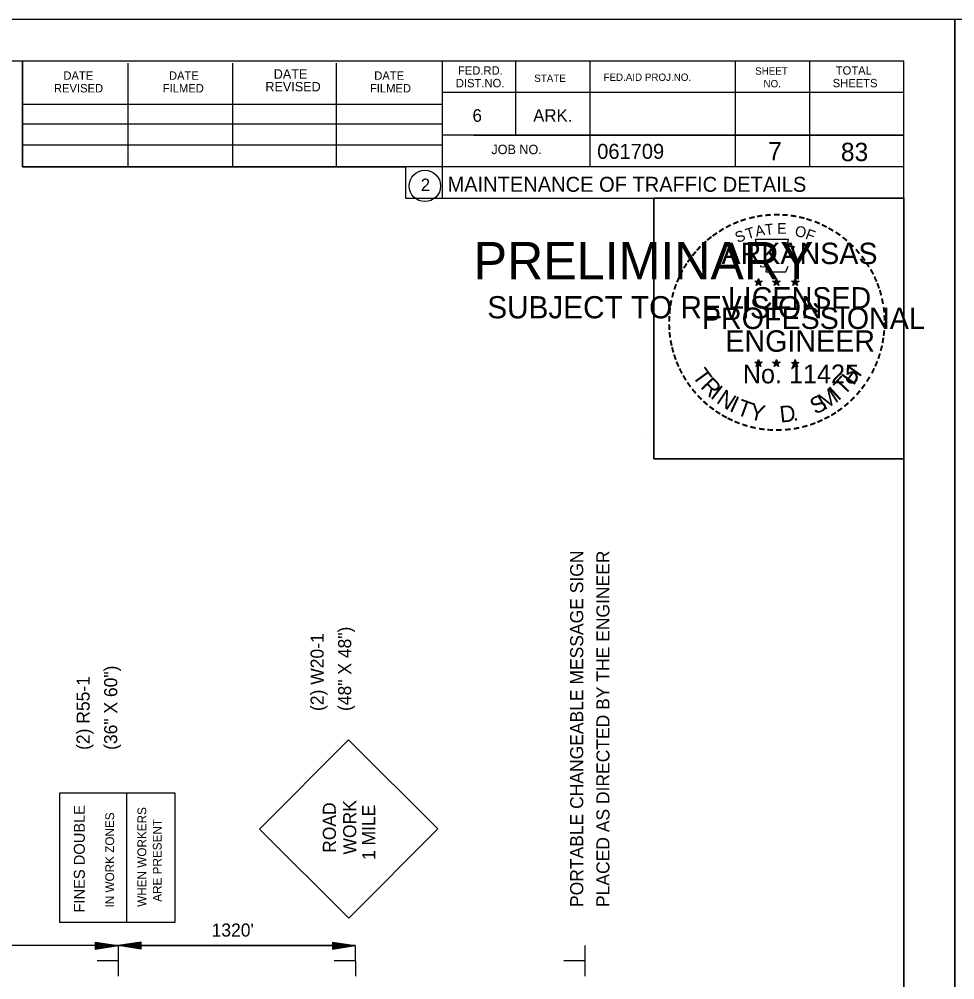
# Model space of a CAD drawing. Extents: x 1397271 to 1411271, y 376395 to 377888.
# Drawn here: x 1398993 to 1399604, y 377260 to 377888 of the extents above; entities that cross this region are included whole.
import ezdxf

# ---------------------------------------------------------------- set-up
doc = ezdxf.new("R2010")
doc.units = 0
for name, color, linetype in [('Default', 7, 'Continuous'), ('R_Border', 7, 'Continuous'), ('R_Border PE', 7, 'Continuous'), ('R_Border Prem', 7, 'Continuous'), ('R_Draft', 7, 'Continuous'), ('R_MOT', 7, 'Continuous'), ('R_No Plot', 7, 'Continuous')]:
    doc.layers.add(name, color=color, linetype=linetype)

msp = doc.modelspace()

# ---------------------------------------------------------------- linework, layer by layer
at = {"layer": 'Default'}
for p, q in [((1399057.58, 377282.68), (1398902.58, 377282.68)), ((1399057.58, 377282.68), (1399207.58, 377282.68)), ((1399212.58, 377282.68), (1399057.58, 377282.68))]:
    msp.add_line(p, q, dxfattribs=at)
at = {"layer": 'R_Border'}
for p, q in [((1397357.73, 377860.72), (1399571.03, 377860.72)), ((1398995.2, 377791.56), (1398995.2, 377860.72)), ((1399064.22, 377791.56), (1399064.22, 377859.32)), ((1399132.54, 377791.56), (1399132.54, 377859.32)), ((1399200.3, 377791.56), (1399200.3, 377859.32)), ((1399269.32, 377860.72), (1399269.32, 377771.12)), ((1399317.2, 377860.72), (1399317.2, 377812.14)), ((1399365.79, 377860.72), (1399365.79, 377791.56)), ((1399460.85, 377860.72), (1399460.85, 377791.56)), ((1399509.43, 377860.72), (1399509.43, 377791.56)), ((1399571.03, 376422.47), (1399571.03, 377860.72)), ((1399571.03, 377840.14), (1399269.32, 377840.14)), ((1399571.03, 377840.28), (1399571.03, 377840.28)), ((1398995.2, 377832.58), (1399269.32, 377832.58)), ((1398995.2, 377819.56), (1399269.32, 377819.56)), ((1399571.03, 377812.14), (1399269.32, 377812.14)), ((1399290.04, 377812.14), (1399571.03, 377812.14)), ((1398995.2, 377791.56), (1398995.2, 377805.98)), ((1398995.2, 377805.98), (1399269.32, 377805.98)), ((1399571.03, 377791.56), (1398995.2, 377791.56)), ((1399269.32, 377771.12), (1399571.03, 377771.12))]:
    msp.add_line(p, q, dxfattribs=at)
msp.add_circle((1399258.03, 377779.07), 10.27, dxfattribs=at)
at = {"layer": 'R_Border PE'}
for p, q in [((1399476.05, 377718.62), (1399475.76, 377716.85)), ((1399476.05, 377716.06), (1399476.05, 377718.62)), ((1399476.05, 377718.62), (1399476.4, 377716.87)), ((1399487.74, 377718.62), (1399487.46, 377716.85)), ((1399487.74, 377716.06), (1399487.74, 377718.62)), ((1399487.74, 377718.62), (1399488.09, 377716.87)), ((1399500.09, 377718.53), (1399499.8, 377716.77)), ((1399500.09, 377715.98), (1399500.09, 377718.53)), ((1399500.09, 377718.53), (1399500.43, 377716.78)), ((1399473.61, 377716.84), (1399476.05, 377716.06)), ((1399473.61, 377716.84), (1399475.38, 377716.53)), ((1399473.61, 377716.84), (1399475.27, 377715.99)), ((1399474.54, 377713.98), (1399476.05, 377716.06)), ((1399474.54, 377713.98), (1399475.42, 377715.69)), ((1399474.54, 377713.98), (1399476.04, 377715.5)), ((1399477.54, 377713.98), (1399476.04, 377715.48)), ((1399478.48, 377716.84), (1399476.05, 377716.06)), ((1399477.54, 377713.98), (1399476.05, 377716.06)), ((1399478.48, 377716.84), (1399476.48, 377716.5)), ((1399477.54, 377713.98), (1399476.58, 377716.02)), ((1399478.48, 377716.84), (1399477.05, 377716.13)), ((1399485.3, 377716.84), (1399487.74, 377716.06)), ((1399485.3, 377716.84), (1399487.07, 377716.53)), ((1399485.3, 377716.84), (1399486.96, 377715.99)), ((1399486.23, 377713.98), (1399487.74, 377716.06)), ((1399486.23, 377713.98), (1399487.11, 377715.69)), ((1399486.23, 377713.98), (1399487.73, 377715.5)), ((1399489.23, 377713.98), (1399487.73, 377715.48)), ((1399490.17, 377716.84), (1399487.74, 377716.06)), ((1399489.23, 377713.98), (1399487.74, 377716.06)), ((1399490.17, 377716.84), (1399488.17, 377716.5)), ((1399489.23, 377713.98), (1399488.27, 377716.02)), ((1399490.17, 377716.84), (1399488.74, 377716.13)), ((1399497.65, 377716.76), (1399500.09, 377715.98)), ((1399497.65, 377716.76), (1399499.42, 377716.44)), ((1399497.65, 377716.76), (1399499.31, 377715.9)), ((1399498.58, 377713.9), (1399500.09, 377715.98)), ((1399498.58, 377713.9), (1399499.46, 377715.61)), ((1399498.58, 377713.9), (1399500.08, 377715.42)), ((1399501.58, 377713.9), (1399500.08, 377715.4)), ((1399502.52, 377716.76), (1399500.09, 377715.98)), ((1399501.58, 377713.9), (1399500.09, 377715.98)), ((1399502.52, 377716.76), (1399500.52, 377716.41)), ((1399501.58, 377713.9), (1399500.62, 377715.94)), ((1399502.52, 377716.76), (1399501.09, 377716.04)), ((1399473.58, 377663.83), (1399476.02, 377663.05)), ((1399473.58, 377663.83), (1399475.35, 377663.51)), ((1399473.58, 377663.83), (1399475.24, 377662.97)), ((1399474.51, 377660.97), (1399476.02, 377663.05)), ((1399474.51, 377660.97), (1399475.39, 377662.68)), ((1399474.51, 377660.97), (1399476.01, 377662.49)), ((1399476.02, 377665.61), (1399475.74, 377663.84)), ((1399477.52, 377660.97), (1399476.01, 377662.47)), ((1399476.02, 377663.05), (1399476.02, 377665.61)), ((1399476.02, 377665.61), (1399476.37, 377663.86)), ((1399478.45, 377663.83), (1399476.02, 377663.05)), ((1399477.52, 377660.97), (1399476.02, 377663.05)), ((1399478.45, 377663.83), (1399476.45, 377663.49)), ((1399477.52, 377660.97), (1399476.56, 377663.01)), ((1399478.45, 377663.83), (1399477.03, 377663.11)), ((1399485.26, 377663.83), (1399487.71, 377663.05)), ((1399485.26, 377663.83), (1399487.04, 377663.51)), ((1399485.26, 377663.83), (1399486.92, 377662.97)), ((1399486.2, 377660.97), (1399487.71, 377663.05)), ((1399486.2, 377660.97), (1399487.08, 377662.68)), ((1399486.2, 377660.97), (1399487.69, 377662.49)), ((1399487.71, 377665.61), (1399487.42, 377663.84)), ((1399489.2, 377660.97), (1399487.69, 377662.47)), ((1399487.71, 377663.05), (1399487.71, 377665.61)), ((1399487.71, 377665.61), (1399488.05, 377663.86)), ((1399490.14, 377663.83), (1399487.71, 377663.05)), ((1399489.2, 377660.97), (1399487.71, 377663.05)), ((1399490.14, 377663.83), (1399488.13, 377663.49)), ((1399489.2, 377660.97), (1399488.24, 377663.01)), ((1399490.14, 377663.83), (1399488.71, 377663.11)), ((1399497.63, 377663.76), (1399500.08, 377662.98)), ((1399497.63, 377663.76), (1399499.4, 377663.44)), ((1399497.63, 377663.76), (1399499.29, 377662.9)), ((1399498.56, 377660.9), (1399500.08, 377662.98)), ((1399498.56, 377660.9), (1399499.45, 377662.61)), ((1399498.56, 377660.9), (1399500.06, 377662.42)), ((1399500.08, 377665.54), (1399499.79, 377663.77)), ((1399501.57, 377660.9), (1399500.06, 377662.4)), ((1399500.08, 377662.98), (1399500.08, 377665.54)), ((1399500.08, 377665.54), (1399500.42, 377663.79)), ((1399502.51, 377663.76), (1399500.08, 377662.98)), ((1399501.57, 377660.9), (1399500.08, 377662.98)), ((1399502.51, 377663.76), (1399500.5, 377663.42)), ((1399501.57, 377660.9), (1399500.61, 377662.94)), ((1399502.51, 377663.76), (1399501.08, 377663.04))]:
    msp.add_line(p, q, dxfattribs=at)
for points in [[(1399473.9, 377743.99), (1399475.78, 377738.2)], [(1399498.47, 377737.53), (1399499.47, 377739.52), (1399494.67, 377739.35), (1399495.71, 377743.99), (1399473.9, 377743.99)], [(1399477.34, 377727.03), (1399477.34, 377726.42), (1399481.28, 377726.28), (1399480.9, 377722.97), (1399493.99, 377722.97), (1399495.4, 377726.72)], [(1399476.05, 377718.62), (1399477.54, 377713.98), (1399473.61, 377716.84), (1399478.48, 377716.84), (1399474.54, 377713.98), (1399476.05, 377718.62)], [(1399487.74, 377718.62), (1399489.23, 377713.98), (1399485.3, 377716.84), (1399490.17, 377716.84), (1399486.23, 377713.98), (1399487.74, 377718.62)], [(1399500.09, 377718.53), (1399501.58, 377713.9), (1399497.65, 377716.76), (1399502.52, 377716.76), (1399498.58, 377713.9), (1399500.09, 377718.53)], [(1399476.02, 377665.61), (1399477.52, 377660.97), (1399473.58, 377663.83), (1399478.45, 377663.83), (1399474.51, 377660.97), (1399476.02, 377665.61)], [(1399487.71, 377665.61), (1399489.2, 377660.97), (1399485.26, 377663.83), (1399490.14, 377663.83), (1399486.2, 377660.97), (1399487.71, 377665.61)], [(1399500.08, 377665.54), (1399501.57, 377660.9), (1399497.63, 377663.76), (1399502.51, 377663.76), (1399498.56, 377660.9), (1399500.08, 377665.54)]]:
    msp.add_lwpolyline(points, dxfattribs=at)
for centre, radius in [((1399476.04, 377716.06), 1.21), ((1399476.04, 377716.06), 1.01), ((1399476.04, 377716.06), 0.81), ((1399476.04, 377716.06), 0.694), ((1399476.04, 377716.06), 0.523), ((1399476.04, 377716.06), 0.347), ((1399476.04, 377716.06), 0.208), ((1399487.74, 377716.06), 1.21), ((1399487.74, 377716.06), 1.01), ((1399487.74, 377716.06), 0.81), ((1399487.74, 377716.06), 0.694), ((1399487.74, 377716.06), 0.523), ((1399487.74, 377716.06), 0.347), ((1399487.74, 377716.06), 0.208), ((1399500.08, 377715.97), 1.21), ((1399500.08, 377715.97), 1.01), ((1399500.08, 377715.97), 0.81), ((1399500.08, 377715.97), 0.694), ((1399500.08, 377715.97), 0.523), ((1399500.08, 377715.97), 0.347), ((1399500.08, 377715.97), 0.208), ((1399476.02, 377663.05), 1.21), ((1399476.02, 377663.05), 1.01), ((1399476.02, 377663.05), 0.81), ((1399476.02, 377663.05), 0.694), ((1399476.02, 377663.05), 0.523), ((1399476.02, 377663.05), 0.347), ((1399476.02, 377663.05), 0.208), ((1399487.7, 377663.05), 1.21), ((1399487.7, 377663.05), 1.01), ((1399487.7, 377663.05), 0.81), ((1399487.7, 377663.05), 0.694), ((1399487.7, 377663.05), 0.523), ((1399487.7, 377663.05), 0.347), ((1399487.7, 377663.05), 0.208), ((1399500.07, 377662.98), 1.21), ((1399500.07, 377662.98), 1.01), ((1399500.07, 377662.98), 0.81), ((1399500.07, 377662.98), 0.694), ((1399500.07, 377662.98), 0.523), ((1399500.07, 377662.98), 0.347), ((1399500.07, 377662.98), 0.208)]:
    msp.add_circle(centre, radius, dxfattribs=at)
at = {"layer": 'R_Draft'}
for p, q in [((1399042.58, 377284.93), (1399057.58, 377282.68)), ((1399042.58, 377284.93), (1399042.58, 377280.43)), ((1399072.58, 377284.93), (1399057.58, 377282.68)), ((1399072.58, 377280.43), (1399072.58, 377284.93)), ((1399197.58, 377284.93), (1399212.58, 377282.68)), ((1399197.58, 377284.93), (1399197.58, 377280.43)), ((1399042.58, 377284.56), (1399055.08, 377282.68)), ((1399042.58, 377284.17), (1399052.5, 377282.68)), ((1399042.58, 377283.8), (1399050, 377282.68)), ((1399042.58, 377283.41), (1399047.46, 377282.68)), ((1399042.58, 377283.03), (1399044.95, 377282.68)), ((1399042.58, 377280.43), (1399057.58, 377282.68)), ((1399042.58, 377281.95), (1399047.46, 377282.68)), ((1399042.58, 377281.19), (1399052.5, 377282.68)), ((1399042.58, 377280.81), (1399055.08, 377282.68)), ((1399042.58, 377281.56), (1399050, 377282.68)), ((1399042.58, 377282.33), (1399044.95, 377282.68)), ((1399072.58, 377280.43), (1399057.58, 377282.68)), ((1399072.58, 377284.56), (1399060.09, 377282.68)), ((1399072.58, 377280.81), (1399060.09, 377282.68)), ((1399072.58, 377284.17), (1399062.67, 377282.68)), ((1399072.58, 377281.19), (1399062.67, 377282.68)), ((1399072.58, 377283.8), (1399065.17, 377282.68)), ((1399072.58, 377281.56), (1399065.17, 377282.68)), ((1399072.58, 377283.42), (1399067.71, 377282.68)), ((1399072.58, 377281.95), (1399067.71, 377282.68)), ((1399072.58, 377283.03), (1399070.21, 377282.68)), ((1399072.58, 377282.33), (1399070.21, 377282.68)), ((1399197.58, 377284.56), (1399210.08, 377282.68)), ((1399197.58, 377284.17), (1399207.5, 377282.68)), ((1399197.58, 377283.8), (1399205, 377282.68)), ((1399197.58, 377283.41), (1399202.46, 377282.68)), ((1399197.58, 377283.03), (1399199.95, 377282.68)), ((1399197.58, 377280.43), (1399212.58, 377282.68)), ((1399197.58, 377281.95), (1399202.46, 377282.68)), ((1399197.58, 377281.19), (1399207.5, 377282.68)), ((1399197.58, 377280.81), (1399210.08, 377282.68)), ((1399197.58, 377281.56), (1399205, 377282.68)), ((1399197.58, 377282.33), (1399199.95, 377282.68))]:
    msp.add_line(p, q, dxfattribs=at)
at = {"layer": 'R_MOT'}
for p, q in [((1399208.05, 377417.14), (1399149.94, 377358.77)), ((1399208.05, 377417.14), (1399266.42, 377358.98)), ((1399063.16, 377382.35), (1399063.16, 377297.93)), ((1399149.94, 377358.77), (1399208.26, 377300.61)), ((1399266.42, 377358.98), (1399208.26, 377300.61)), ((1399057.58, 377282.68), (1399057.67, 377262.83)), ((1399212.58, 377282.68), (1399212.67, 377262.83)), ((1399362.58, 377282.68), (1399362.67, 377262.83)), ((1399057.63, 377272.8), (1399043.79, 377272.74)), ((1399212.63, 377272.8), (1399198.79, 377272.74)), ((1399362.63, 377272.8), (1399348.79, 377272.74))]:
    msp.add_line(p, q, dxfattribs=at)
msp.add_lwpolyline([(1399019.38, 377297.93), (1399094.83, 377297.93), (1399094.83, 377382.35), (1399019.38, 377382.35)], close=True, dxfattribs=at)
at = {"layer": 'R_No Plot'}
for p, q in [((1397270.92, 377887.98), (1399604.3, 377887.98)), ((1399403.25, 377613.86), (1399403.25, 377613.86))]:
    msp.add_line(p, q, dxfattribs=at)
for points in [[(1397270.87, 377887.98), (1399604.3, 377887.98), (1399604.3, 376394.59), (1397270.87, 376394.59)], [(1399604.3, 377887.98), (1401937.72, 377887.98), (1401937.72, 376394.59), (1399604.3, 376394.59)], [(1398995.2, 377860.72), (1398995.2, 377791.56), (1399245.33, 377791.56), (1399245.33, 377771.12), (1399407.73, 377771.12), (1399407.73, 377600.79), (1399571.03, 377600.79), (1399571.03, 376422.47), (1397357.73, 376422.47), (1397357.73, 377860.72)], [(1399407.73, 377771.34), (1399571.03, 377771.34), (1399571.03, 377600.79), (1399407.73, 377600.79)]]:
    msp.add_lwpolyline(points, close=True, dxfattribs=at)

# ---------------------------------------------------------------- texts
at = {"layer": 'Default'}
for s, p in [('PORTABLE CHANGEABLE MESSAGE SIGN', (1399361.51, 377307.91)), ('PLACED AS DIRECTED BY THE ENGINEER', (1399378.66, 377307.91))]:
    msp.add_text(s, height=8.54, rotation=90, dxfattribs=at).set_placement(p)
msp.add_text("1320'", height=8.54, dxfattribs=at).set_placement((1399118.69, 377288.59))
at = {"layer": 'R_Border'}
for s, height, p in [('FED.RD.', 5.474, (1399279.68, 377851.76)), ('SHEET', 4.788, (1399473.87, 377851.76)), ('TOTAL', 5.474, (1399526.51, 377851.76)), ('DATE', 5.474, (1399021.8, 377848.4)), ('DATE', 5.474, (1399090.82, 377848.4)), ('DATE', 6.155, (1399159.28, 377849.1)), ('DATE', 5.474, (1399224.94, 377848.4)), ('STATE', 4.788, (1399329.52, 377847)), ('FED.AID PROJ.NO.', 4.7881, (1399374.75, 377847.7)), ('REVISED', 5.474, (1399015.64, 377840.14)), ('FILMED', 5.474, (1399086.76, 377840.14)), ('REVISED', 6.155, (1399153.82, 377840.84)), ('FILMED', 5.474, (1399222.14, 377840.14)), ('DIST.NO.', 5.474, (1399278.28, 377843.5)), ('NO.', 4.788, (1399479.33, 377843.5)), ('SHEETS', 5.474, (1399524.55, 377843.5)), ('6', 8.21, (1399289.2, 377820.96)), ('ARK.', 8.206, (1399328.82, 377820.96)), ('JOB NO.', 6.155, (1399301.52, 377799.82)), ('061709', 9.8, (1399370.66, 377796.74)), ('2', 8.21, (1399255.35, 377775.66)), ('MAINTENANCE OF TRAFFIC DETAILS', 9.8002, (1399272.84, 377775.2))]:
    msp.add_text(s, height=height, dxfattribs=at).set_placement(p)
at = {"layer": 'R_Border PE'}
for s, height, rotation, p in [('-', 11.2, 24.30721, (1399460.69, 377749.99)), ('-', 11.2, 19.17608, (1399465.13, 377751.88)), ('-', 11.2, 13.63015, (1399470.38, 377753.56)), ('-', 11.2, 10.21935, (1399475.13, 377754.7)), ('-', 11.2, 5.89682, (1399480.23, 377755.47)), ('-', 11.2, 0.18623, (1399485.63, 377755.97)), ('-', 11.2, 357.74304, (1399490.69, 377755.88)), ('-', 11.2, 352.16172, (1399495.9, 377755.49)), ('-', 11.2, 347.20489, (1399500.94, 377754.69)), ('-', 11.2, 342.3362, (1399505.38, 377753.61)), ('-', 11.2, 337.85509, (1399510.53, 377752.04)), ('-', 11.2, 34.06357, (1399452.08, 377745.18)), ('-', 11.2, 28.79182, (1399456.26, 377747.77)), ('S', 7, 21.59401, (1399462.38, 377741.73)), ('T', 7, 16.4036, (1399468.78, 377744.05)), ('A', 7, 11.21318, (1399474.56, 377745.81)), ('T', 7, 6.02276, (1399480.5, 377746.97)), ('E', 7, 0.83234, (1399488.24, 377747.74)), ('O', 7, 350.4515, (1399499.47, 377746.27)), ('F', 7, 340.07066, (1399506.14, 377744.67)), ('-', 11.2, 334.12109, (1399514.94, 377750.15)), ('-', 11.2, 329.64089, (1399519, 377748.17)), ('-', 11.2, 325.86266, (1399523.5, 377745.64)), ('-', 11.2, 42.96224, (1399441.67, 377736.85)), ('-', 11.2, 38.95066, (1399444.7, 377739.77)), ('-', 11.2, 36.23174, (1399448.04, 377742.42)), ('-', 11.2, 320.52971, (1399527.77, 377742.66)), ('-', 11.2, 48.42305, (1399438.54, 377733.51)), ('-', 11.2, 315.57859, (1399531.96, 377739.24)), ('-', 11.2, 309.87973, (1399535.94, 377735.39)), ('-', 11.2, 54.23247, (1399432.82, 377726.14)), ('-', 11.2, 50.61417, (1399435.72, 377730.11)), ('-', 11.2, 306.65218, (1399539.62, 377731.18)), ('-', 11.2, 62.87135, (1399428.36, 377718.15)), ('-', 11.2, 58.07063, (1399430.55, 377722.45)), ('-', 9.8, 303.67529, (1399543.02, 377727.2)), ('-', 11.2, 299.66835, (1399545.25, 377722.95)), ('-', 11.2, 67.77427, (1399426.55, 377713.87)), ('-', 11.2, 294.66279, (1399547.52, 377718.67)), ('-', 11.2, 72.39447, (1399425.01, 377709.46)), ('-', 11.2, 290.57283, (1399549.32, 377714.63)), ('-', 11.2, 75.46096, (1399423.63, 377704.46)), ('-', 11.2, 285.12326, (1399550.96, 377710.57)), ('-', 11.2, 280.54934, (1399552.36, 377705.37)), ('-', 11.2, 85.18634, (1399422.18, 377694.64)), ('-', 11.2, 81.20126, (1399422.71, 377699.47)), ('-', 11.2, 276.59616, (1399553.49, 377700)), ('-', 11.2, 89.06224, (1399422, 377689.73)), ('-', 11.2, 274.33011, (1399553.91, 377694.94)), ('-', 11.2, 94.19588, (1399422.25, 377684.65)), ('-', 11.2, 269.94067, (1399554.15, 377690.52)), ('-', 11.2, 98.94793, (1399422.75, 377679.99)), ('-', 11.2, 263.5172, (1399554.02, 377685.86)), ('-', 11.2, 101.71495, (1399423.7, 377674.85)), ('-', 11.2, 255.7626, (1399552.75, 377676.53)), ('-', 11.2, 260.99529, (1399553.52, 377681.28)), ('-', 11.2, 105.45785, (1399424.83, 377670.69)), ('-', 11.2, 109.08742, (1399426.34, 377666.27)), ('-', 11.2, 252.86809, (1399551.48, 377671.49)), ('-', 11.2, 114.06432, (1399428.11, 377662.1)), ('H', 10.78, 54.60883, (1399538.18, 377648.16)), ('-', 11.2, 247.88866, (1399549.92, 377666.78)), ('-', 11.2, 115.72885, (1399430.25, 377657.77)), ('-', 11.2, 120.44712, (1399432.75, 377653.67)), ('T', 10.78, 306.04056, (1399432.34, 377654.92)), ('-', 11.2, 244.61971, (1399548.09, 377662.38)), ('-', 11.2, 125.89344, (1399435.57, 377649.74)), ('R', 10.78, 314.00497, (1399437.68, 377647.58)), ('T', 10.78, 46.64442, (1399531.96, 377641.57)), ('-', 11.2, 233.84524, (1399542.52, 377652.54)), ('-', 11.2, 239.07125, (1399545.33, 377657.12)), ('-', 11.2, 130.71812, (1399438.8, 377645.88)), ('-', 11.2, 134.22381, (1399442.42, 377642.07)), ('I', 10.78, 321.96938, (1399443.98, 377641.06)), ('N', 10.78, 326.50021, (1399447.95, 377637.76)), ('M', 10.78, 32.65632, (1399519.04, 377632.29)), ('I', 10.78, 42.11359, (1399528.02, 377638.22)), ('-', 11.2, 231.25377, (1399539.51, 377648.58)), ('-', 11.2, 138.93382, (1399446.1, 377638.82)), ('I', 10.78, 335.36034, (1399456.41, 377632.26)), ('T', 10.78, 339.89117, (1399461.04, 377629.96)), ('Y', 10.78, 347.85558, (1399469.56, 377626.85)), ('S', 10.78, 26.9312, (1399513.16, 377629.45)), ('-', 11.2, 221.08509, (1399532.5, 377641.07)), ('-', 11.2, 225.76533, (1399536.15, 377644.63)), ('-', 11.2, 144.64634, (1399449.99, 377635.98)), ('-', 11.2, 148.08978, (1399453.92, 377633.38)), ('D', 10.78, 6.39691, (1399490.45, 377624.34)), ('-', 11.2, 212.24909, (1399524.92, 377635.06)), ('-', 11.2, 215.73633, (1399528.66, 377637.77)), ('-', 11.2, 151.57039, (1399457.97, 377631.1)), ('-', 11.2, 154.60019, (1399461.62, 377629.37)), ('-', 11.2, 158.56121, (1399465.99, 377627.6)), ('-', 11.2, 162.79826, (1399470.8, 377626.11)), ('.', 10.78, 13.76417, (1399498.79, 377625.23)), ('-', 11.2, 200.71842, (1399512.31, 377628.49)), ('-', 11.2, 204.25161, (1399516.64, 377630.4)), ('-', 11.2, 207.35684, (1399521.01, 377632.64)), ('-', 11.2, 167.55551, (1399475.81, 377624.96)), ('-', 11.2, 173.11546, (1399481.21, 377624.19)), ('-', 11.2, 176.51827, (1399486.45, 377623.82)), ('-', 11.2, 181.59176, (1399491.65, 377623.95)), ('-', 11.2, 185.81666, (1399497.32, 377624.48)), ('-', 11.2, 191.28576, (1399502.47, 377625.41)), ('-', 11.2, 195.47429, (1399507.57, 377626.8))]:
    msp.add_text(s, height=height, rotation=rotation, dxfattribs=at).set_placement(p)
for s, height, p in [('ARKANSAS', 14, (1399451.87, 377727.97)), ('LICENSED', 14, (1399456.05, 377698.93)), ('DWB', 0.07, (1399475.96, 377716.03)), ('DWB', 0.07, (1399487.65, 377716.03)), ('DWB', 0.07, (1399500, 377715.95)), ('PROFESSIONAL', 14.0002, (1399439.08, 377685.6)), ('ENGINEER', 14, (1399454.39, 377670.72)), ('No. 11425', 12.299, (1399465.79, 377650.07)), ('DWB', 0.07, (1399475.93, 377663.02)), ('DWB', 0.07, (1399487.62, 377663.02)), ('DWB', 0.07, (1399499.99, 377662.95))]:
    msp.add_text(s, height=height, dxfattribs=at).set_placement(p)
at = {"layer": 'R_Border Prem'}
for s, height, p in [('PRELIMINARY', 24.5005, (1399289.89, 377717.92)), ('DWB', 0.07, (1399291.38, 377730.85)), ('SUBJECT TO REVISION', 14.5261, (1399298.81, 377692.52))]:
    msp.add_text(s, height=height, dxfattribs=at).set_placement(p)
at = {"layer": 'R_Draft'}
for s, p in [('7', (1399482.35, 377795.68)), ('83', (1399529.9, 377795.27))]:
    msp.add_text(s, height=12, rotation=360, dxfattribs=at).set_placement(p)
at = {"layer": 'R_MOT'}
for s, height, rotation, p in [('(2) W20-1', 8.54, 90, (1399191.89, 377435.99)), ('(48" X 48")', 8.54, 90, (1399209.89, 377435.99)), ('(36" X 60")', 8.54, 90, (1399056.99, 377410.56)), ('(2) R55-1', 8.54, 90, (1399038.99, 377410.56)), ('FINES DOUBLE', 7.164, 90, (1399035.82, 377304.31)), ('WHEN WORKERS', 5.7314, 90, (1399075.96, 377308.03)), ('ROAD', 8.54, 90.10045, (1399199.9, 377343.31)), ('WORK', 8.54, 90.10034, (1399213.21, 377342.2)), (' 1 MILE', 8.54, 90.0995, (1399225.62, 377335.47)), ('IN WORK ZONES', 5.7302, 90, (1399054.96, 377307.59)), ('ARE PRESENT', 5.7314, 90, (1399086.01, 377311.35))]:
    msp.add_text(s, height=height, rotation=rotation, dxfattribs=at).set_placement(p)

doc.saveas('drawing.dxf')
